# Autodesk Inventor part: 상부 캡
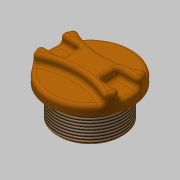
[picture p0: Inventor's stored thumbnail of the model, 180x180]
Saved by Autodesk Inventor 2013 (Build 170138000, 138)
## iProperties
Created: 2016-09
Part Number: 상부 캡
Material: PC/ABS 플라스틱
Document SubType Name: Modeling
Designer: mduedu
Density: 1.493 g/cm^3
Mass: 32.6939 g
Surface Area: 67.9045 cm^2
Volume: 21.8981 cm^3
Author: mduedu
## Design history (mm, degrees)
sketch "스케치1"
  geometry: C1 r 22.5 at (0, 0); 1 further point
  constraints: 1 centre point, 1 coincident
  dimensions: "d0" = 45 diameter of C1
extrude "돌출1" new body sketch "스케치1" distance "d1" = 10; taper "d2" = 0 deg
sketch "스케치2" dims "d4" = 80
  geometry: C1 r 22.5 at (0, 0) reference; 3 further points
  constraints: 3 vertical alignment, 2 other
  dimensions: "d3" = 7 distance of point (0, 7) point (0, 0)
extrude "돌출2" cut sketch "스케치2" distance "d5" = 5; taper "d6" = 0 deg
sketch "스케치3"
  geometry: L1 (-22.5, 0)-(0, 0); L2 (-21.937, 5)-(-10, 5); L3 (-10, 5)-(-10, -5); L4 (-10, -5)-(-21.937, -5); A1 r 22.5 centre (0, 0) between (-19.118, 11.864) and (-19.118, -11.864) reference; A2 r 22.5 centre (0, 0) between (-21.937, 5) and (-21.937, -5); 1 further point
  constraints: 8 end point, 5 point on circle, 2 horizontal, 1 centre point, 1 coincident, 1 parallel, 1 perpendicular, 1 symmetric about line
  dimensions: "d7" = 10 distance from line of L3 point (0, 0); "d8" = 10 distance of L2.end L3.end
extrude "돌출3" cut sketch "스케치3" distance "d9" = 5; taper "d10" = 0 deg
fillet "모깎기1" dims "d11" = 2
fillet "모깎기2" dims "d12" = 2
fillet "모깎기3" dims "d13" = 2
sketch "스케치4"
  geometry: C1 r 17.5 at (0, 0); 1 further point
  constraints: 1 centre point, 1 coincident
  dimensions: "d14" = 35 diameter of C1
extrude "돌출4" join sketch "스케치4" distance "d15" = 17; taper "d16" = 0 deg
sketch "스케치5"
  geometry: C1 r 12.5 at (0, 0); 1 further point
  constraints: 1 centre point, 1 coincident
  dimensions: "d17" = 25 diameter of C1
extrude "돌출5" cut sketch "스케치5" distance "d18" = 10; taper "d19" = 0 deg
fillet "모깎기4" dims "d20" = 3
feature "스레드1" dims "d21" = 10, "d22" = 0
chamfer "모따기1" distance "d23" = 1; stored, may be unused: second distance "d24" = 2, angle "d25" = 45 deg
node "솔리드1"
mirror "대칭1"
mirror "대칭2"
node "투영된 루프1"
